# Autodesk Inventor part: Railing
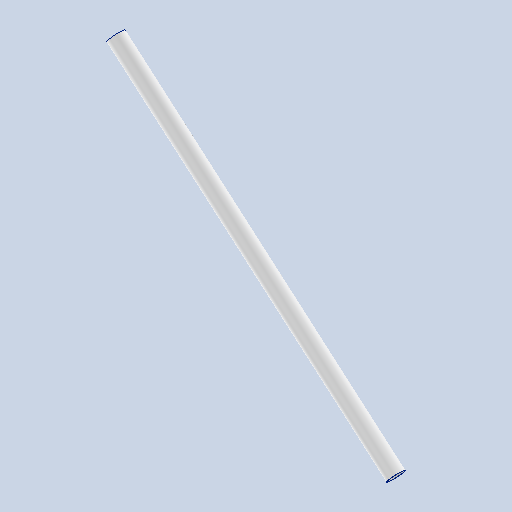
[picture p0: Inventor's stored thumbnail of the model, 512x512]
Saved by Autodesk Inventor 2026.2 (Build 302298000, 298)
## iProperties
Created: 2022-06
Part Number: Railing
Material: Aluminum 6061
Document SubType Name: Modeling
Designer: reaumed
Density: 2.7 g/cm^3
Appearance: Aluminum - Flat
Mass: 1627.16 g
Surface Area: 4753.01 cm^2
Volume: 602.654 cm^3
Author: reaumed
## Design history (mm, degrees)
workplane "Work Plane1"
workplane "Work Plane3"
  workplane "Work Plane2"
workplane "Work Plane4"
revolve "Revolution1" stored, may be unused: angle "d19" = 360 deg
shell "Shell1" dims "d20" = 2.54
body "Solid2"
sketch "Sketch1"
  geometry: L1 (0, 819.15)-(-914.4, 57.15); L2 (-1126.921, 723.9)-(246.904, 723.9) reference; L3 (-1126.921, -190.5)-(246.904, -190.5) reference; L4 (-16.261, 838.663)-(-930.661, 76.663); L5 (-114.3, -250.623)-(-114.3, 1071.007) reference; L6 (0, -250.623)-(0, 1071.007) reference; L7 (0, 819.15)-(-16.261, 838.663); L8 (-914.4, 57.15)-(-930.661, 76.663); L9 (50.643, 758.378)-(-922.53, 66.906); 5 further points
  constraints: 10 end point, 6 point on line, 2 perpendicular, 1 midpoint, 1 parallel
  dimensions: "d4" = 39.8056 deg angle of L1 L3 (= RailingAngle); "d12" = 25.4 distance between parallel lines of L1 L4 (= 0.5 x RailingThickness); "d13" = 0 distance from line of L2 point (-114.3, 723.9); "d14" = 914.4 distance from line of point (-914.4, -61.819) L6 (= RailingRun); "d16" = 1190.28205 distance of L1.start L1.end (= RailingStockLength)
other parameters: "Width" = 762 [user parameter; used in 1 equation term], "Rise" = 190.5 [user parameter; used in 1 equation term], "Run" = 228.6 [user parameter; used in 1 equation term], "RailingWidth" = 76.2 [user parameter], "RailingThickness" = 50.8 [user parameter; used in 2 equation terms], "RailingStockLength" = 1190.28205 [user parameter; used in 1 equation term], "RailingAngle" = 39.8056 deg [user parameter; used in 1 equation term], "d0" = 361.95 (= 0.5 x Width - 0.5 x StringerThickness), "BalusterLength" = 914.4 [user parameter; used in 1 equation term], "d1" = -190.5 (= -Rise), "d2" = 914.4 (= BalusterLength), "d6" = 50.8 (= RailingThickness), "d11" = 114.3 (= 0.5 x Run), "RailingRun" = 914.4 [user parameter; used in 1 equation term], "d15" = 1808.46777 (derived), "StringerThickness" = 38.1 [user parameter; used in 1 equation term]
